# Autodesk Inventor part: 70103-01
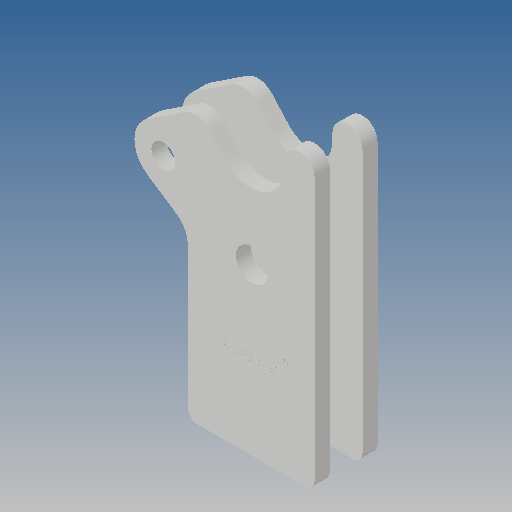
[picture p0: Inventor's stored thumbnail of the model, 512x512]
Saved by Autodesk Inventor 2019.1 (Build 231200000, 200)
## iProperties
Created: 2012-10
Part Number: 70103-01
Material: Ogólny
Document SubType Name: Modeling
Designer: CADENGINEERING4
Density: 1 g/cm^3
Appearance: Domyślna
Author: CADENGINEERING4
Revision Number: ÈÎºÎ
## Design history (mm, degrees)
feature "ÇÐ³ý-À­Éì1"
feature "ÇÐ³ý-À­Éì4"
node "Bryła1"
node "Bryła2"
